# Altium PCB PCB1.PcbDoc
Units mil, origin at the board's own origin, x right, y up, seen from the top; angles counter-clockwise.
Board outline 2228.35 x 2228.35 mil, 2 copper layers (Top Layer, Bottom Layer); 19 components, 12 nets, 62 pads, 0 vias.
Unrouted connection lines stored in the file: 3.
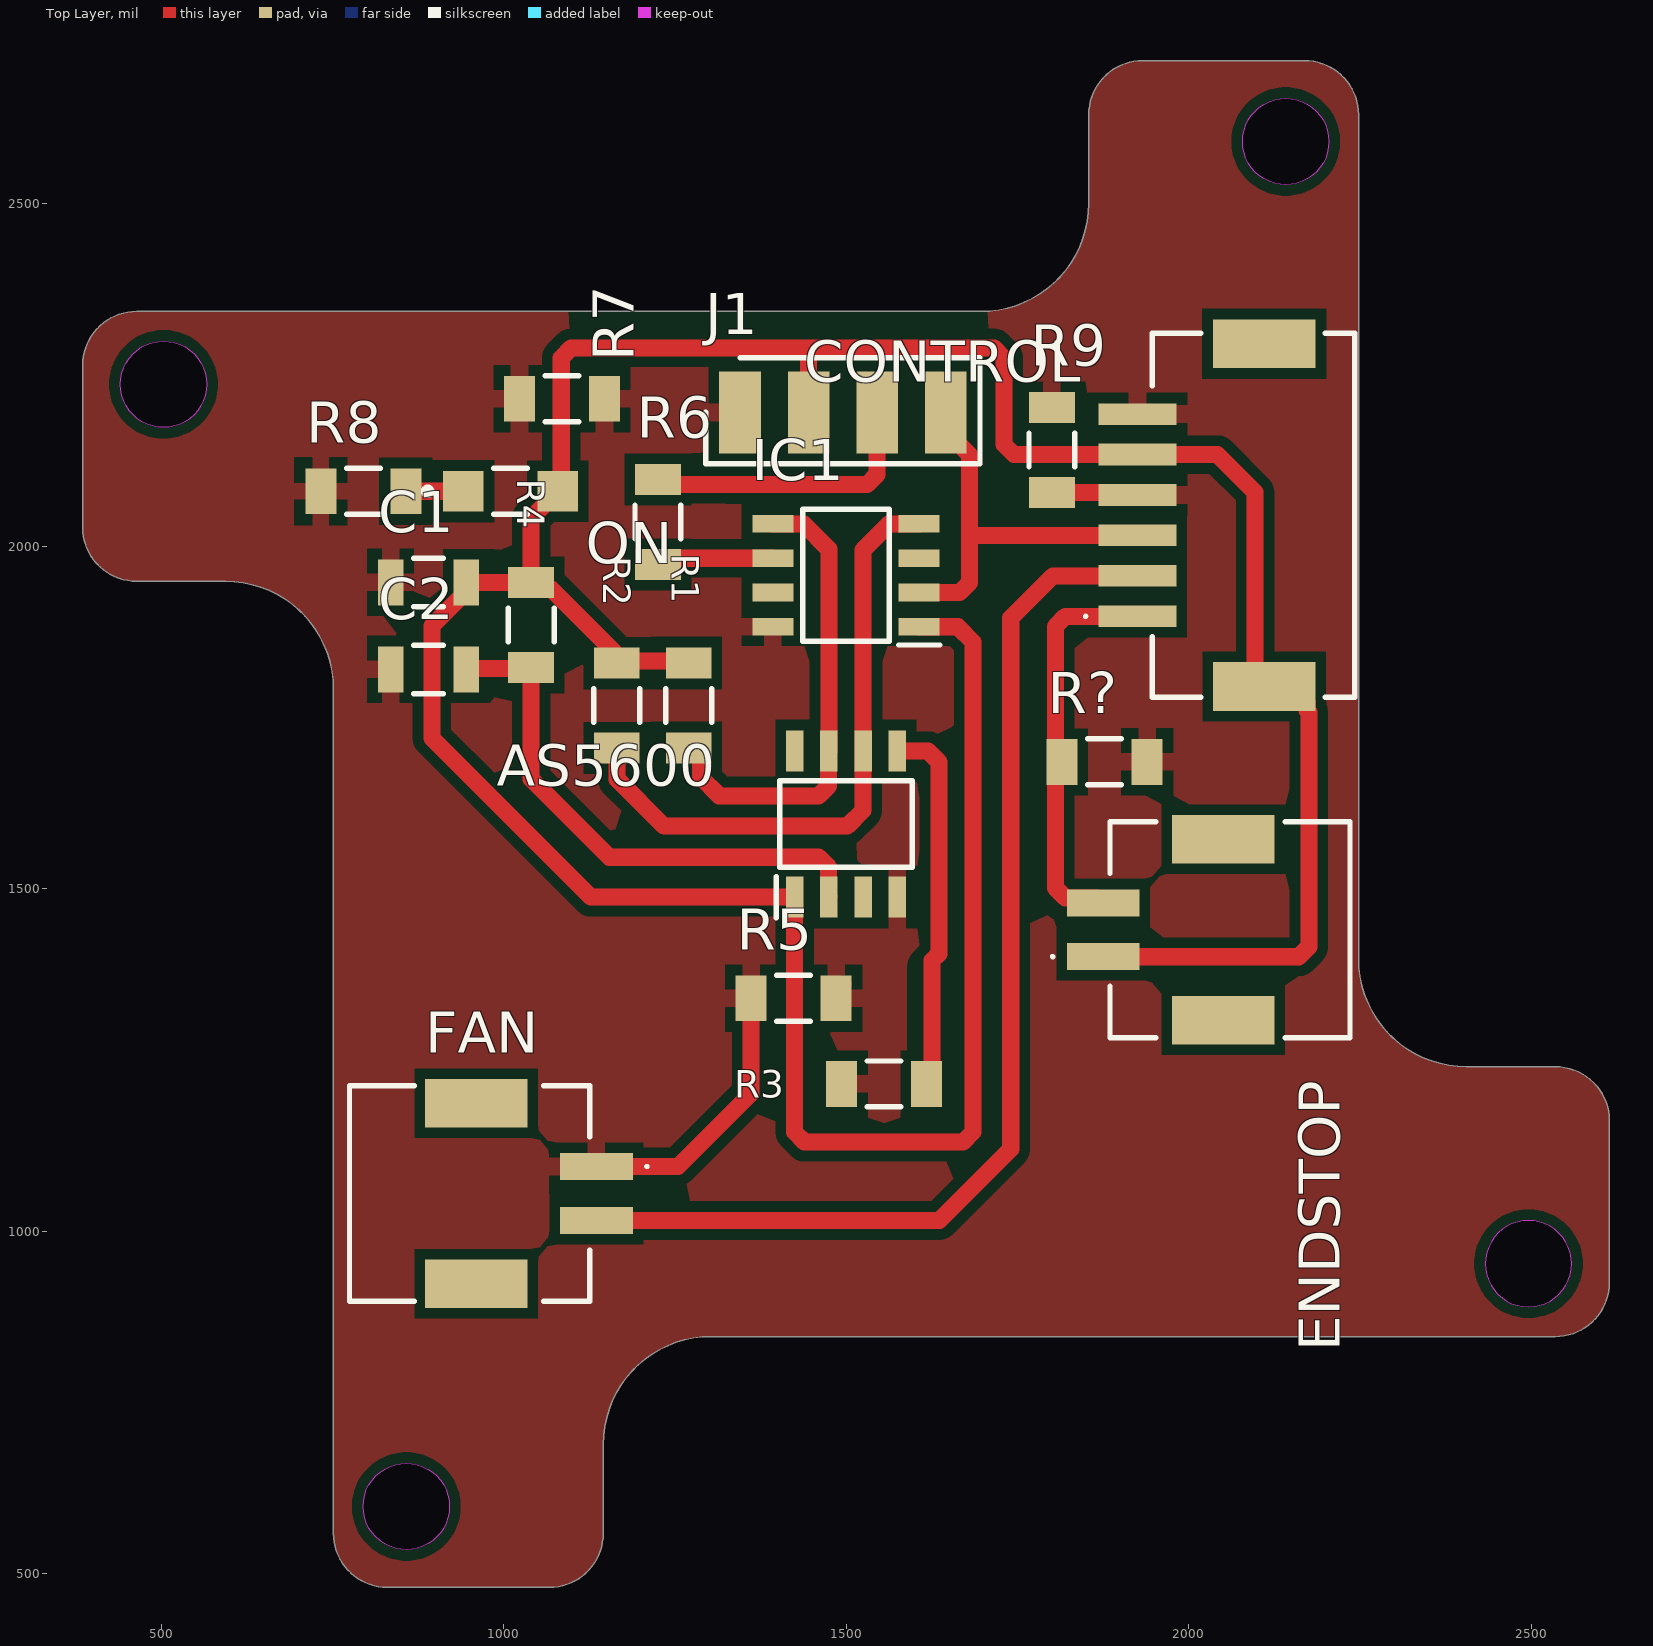
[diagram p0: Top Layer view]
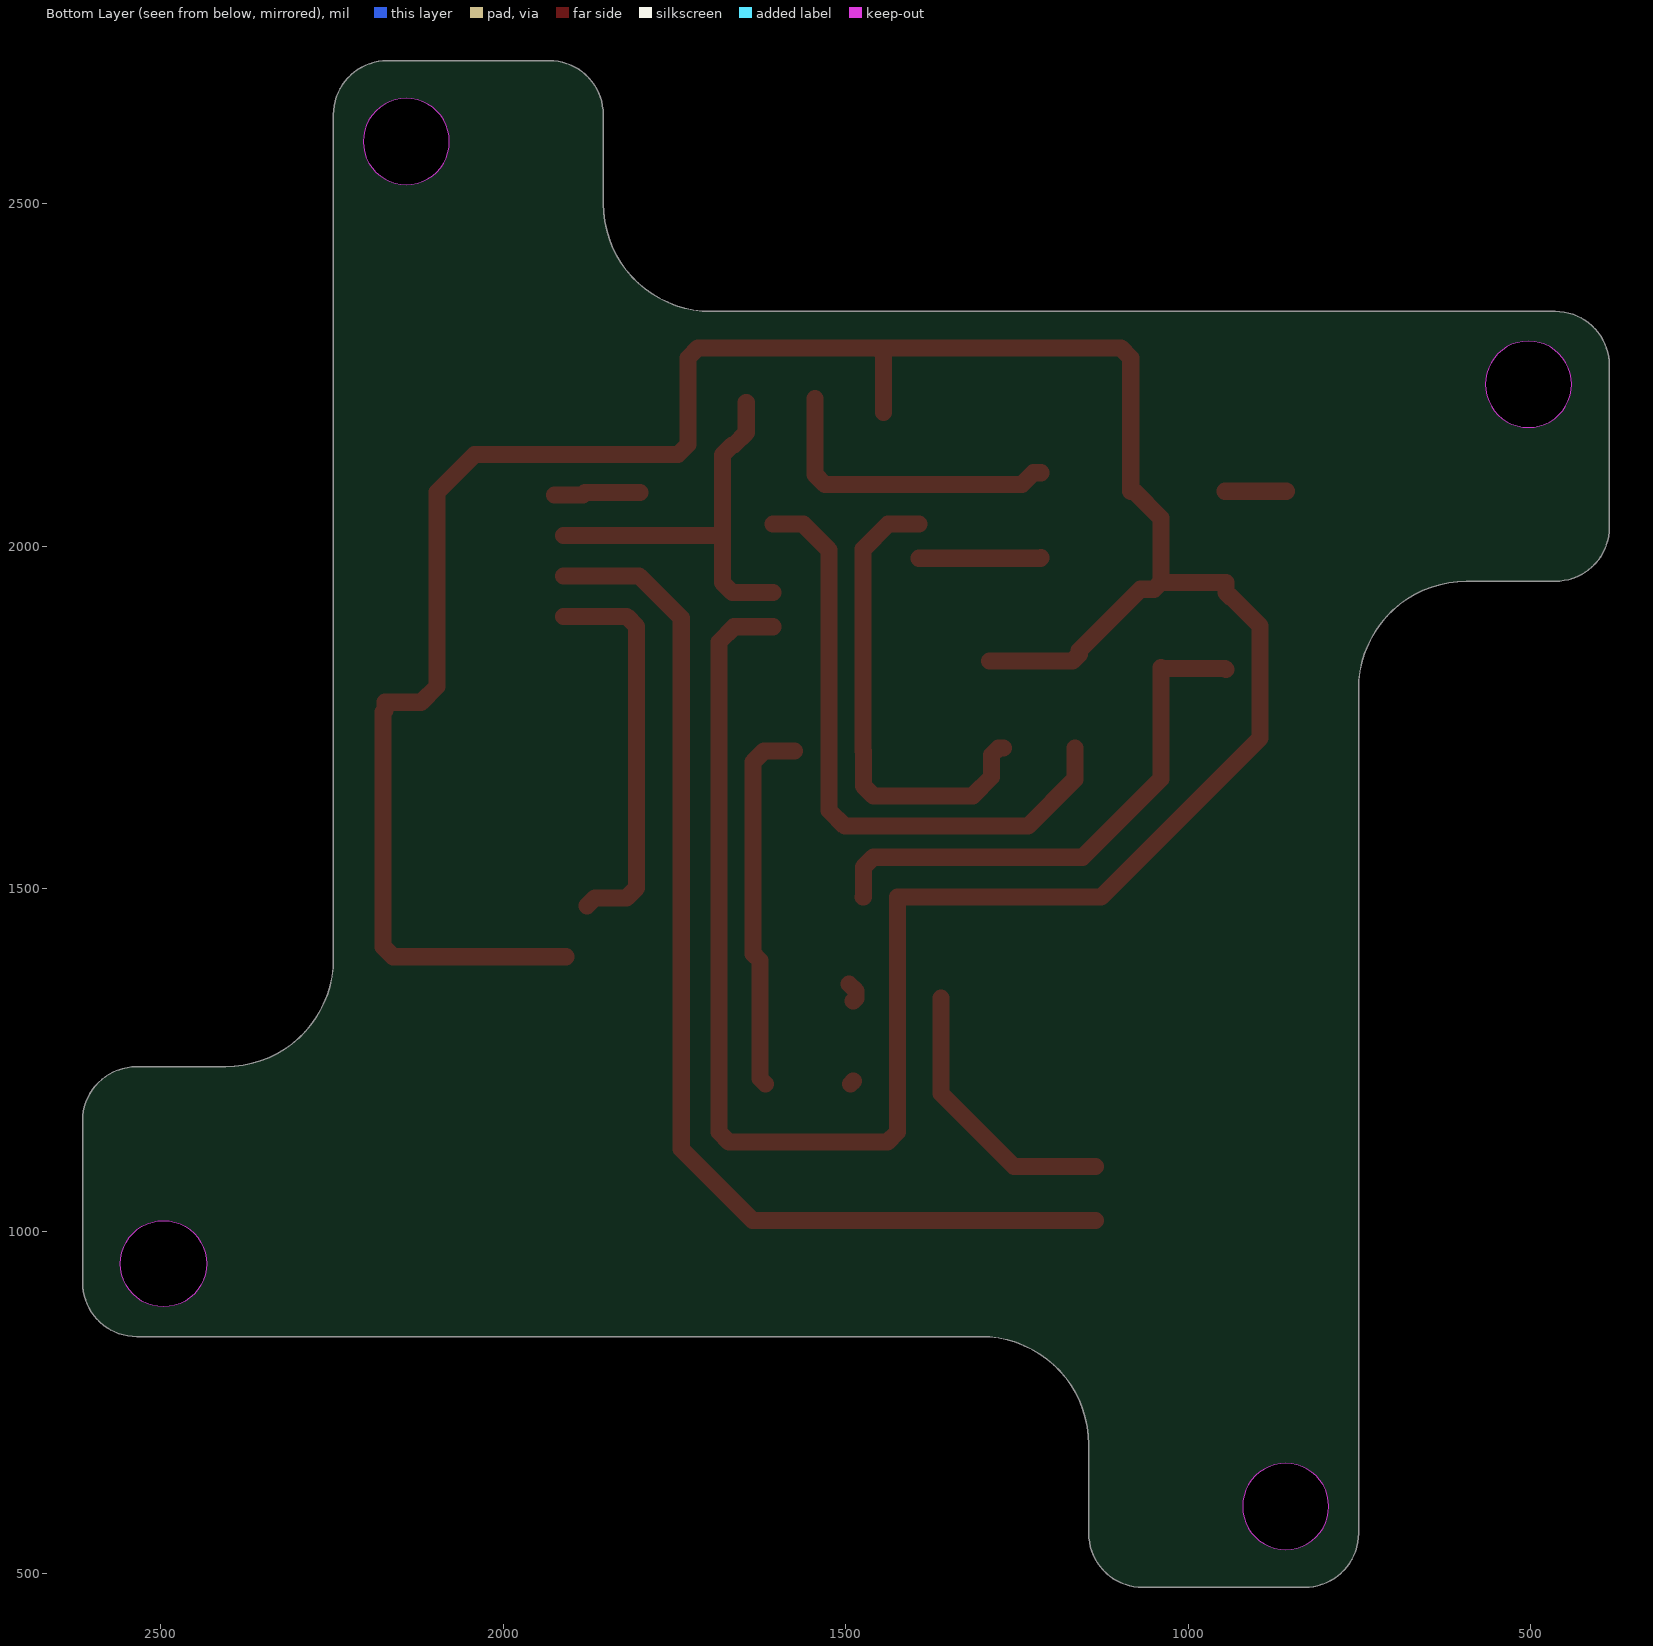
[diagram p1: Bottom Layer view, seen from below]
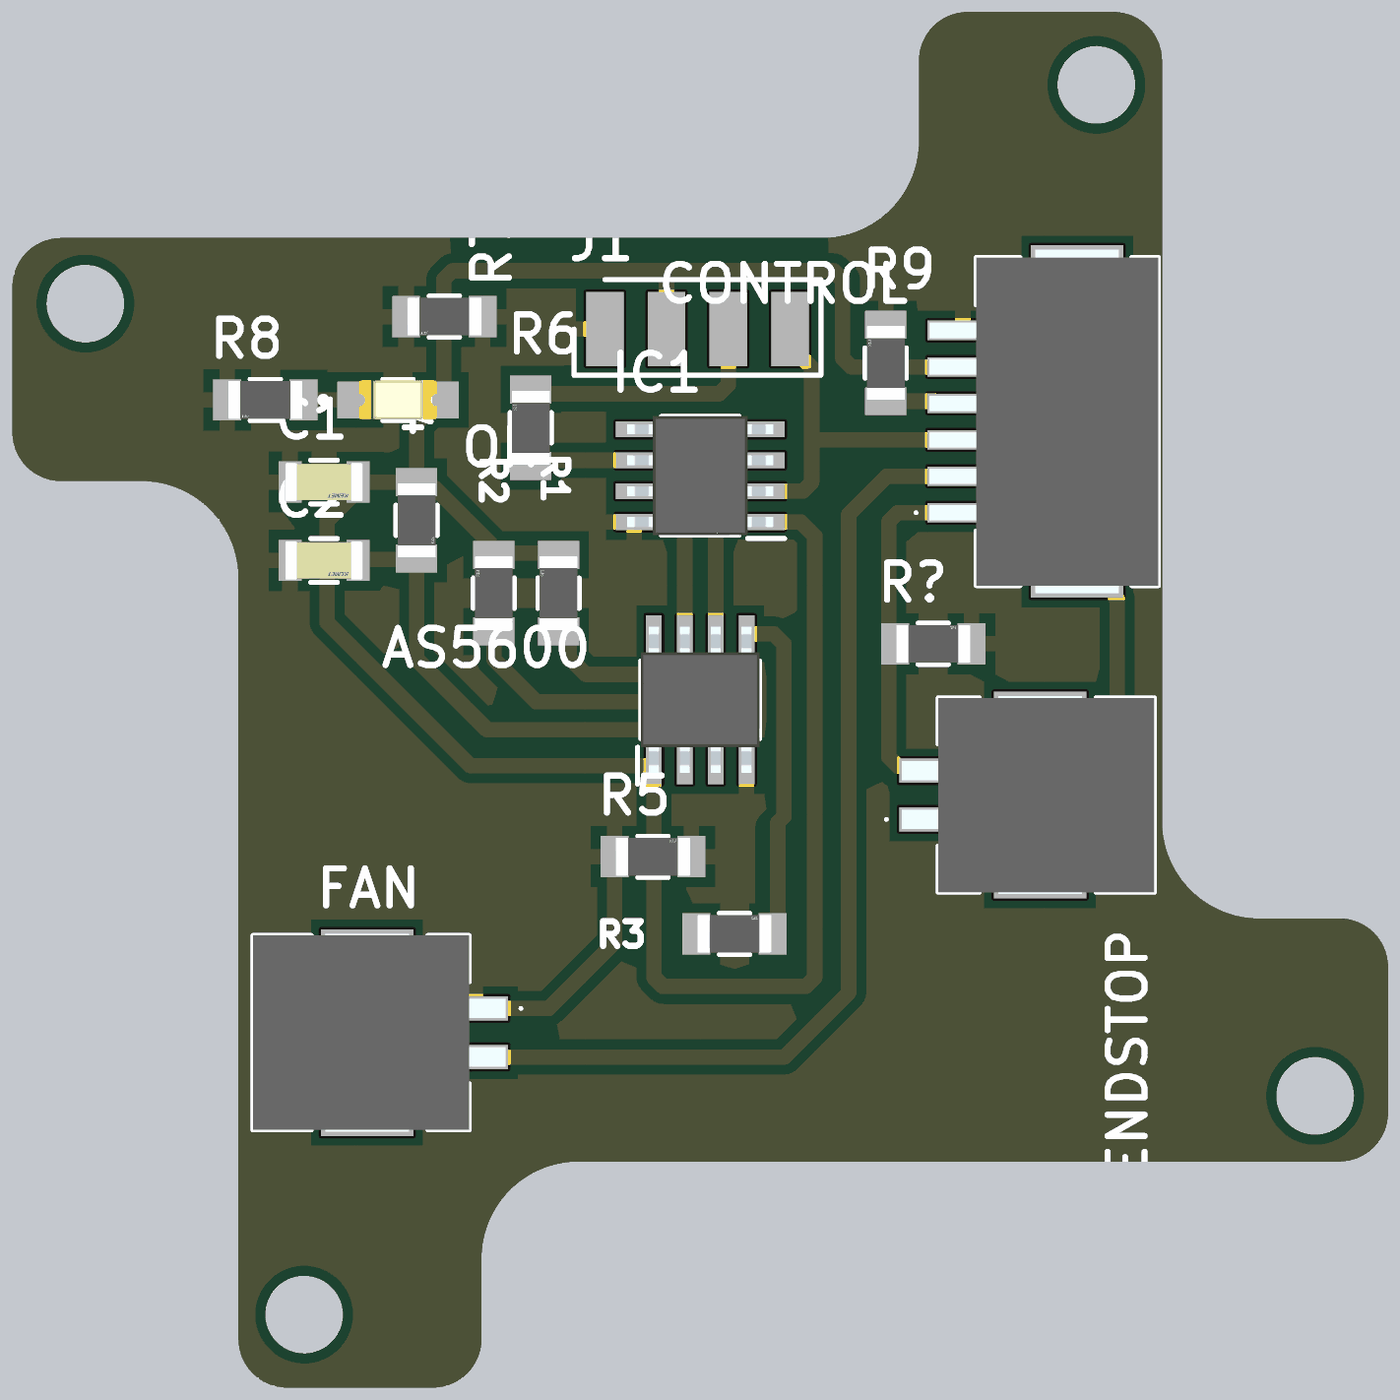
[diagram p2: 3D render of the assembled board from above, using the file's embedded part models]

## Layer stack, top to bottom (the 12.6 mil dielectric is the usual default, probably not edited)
Top Solder: solder mask 0.4, Solder Resist, Dk 3.5
Top Layer: signal copper 1.4
Dielectric 1: dielectric 12.6, FR-4, Dk 4.8
Bottom Layer: signal copper 1.4
Bottom Solder: solder mask 0.4, Solder Resist, Dk 3.5

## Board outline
751.46,558.9 ccw(c830.2,558.9) 830.2,480.16 1066.42,480.16 ccw(c1066.42,558.9) 1145.16,558.9 1145.16,688.82 cw(c1302.64,688.82) 1302.64,846.3 2534.92,846.3 ccw(c2534.92,925.04) 2613.66,925.04 2613.66,1161.26 ccw(c2534.92,1161.26) 2534.92,1240 2405,1240 cw(c2405,1397.48) 2247.52,1397.48 2247.52,2629.76 ccw(c2168.78,2629.76) 2168.78,2708.5 1932.56,2708.5 ccw(c1932.56,2629.76) 1853.82,2629.76 1853.82,2499.84 cw(c1696.34,2499.84) 1696.34,2342.36 464.06,2342.36 ccw(c464.06,2263.62) 385.31,2263.62 385.31,2027.4 ccw(c464.06,2027.4) 464.06,1948.66 593.98,1948.66 cw(c593.98,1791.18) 751.46,1791.18
cut-out: 2432.56,952.6 ccw(c2495.55,952.6) 2495.55,889.61 ccw(c2495.55,952.6) 2558.54,952.6 ccw(c2495.55,952.6) 2495.55,1015.59 ccw(c2495.55,952.6)
cut-out: 2141.22,2527.4 cw(c2141.22,2590.39) 2078.23,2590.39 cw(c2141.22,2590.39) 2141.22,2653.39 cw(c2141.22,2590.39) 2204.21,2590.39 cw(c2141.22,2590.39)
cut-out: 794.76,598.27 cw(c857.76,598.27) 857.76,661.26 cw(c857.76,598.27) 920.75,598.27 cw(c857.76,598.27) 857.76,535.28 cw(c857.76,598.27)
cut-out: 503.43,2173.07 cw(c503.43,2236.06) 440.43,2236.06 cw(c503.43,2236.06) 503.43,2299.06 cw(c503.43,2236.06) 566.42,2236.06 cw(c503.43,2236.06)

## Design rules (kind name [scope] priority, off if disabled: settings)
Clearance [All] p1: gap=15.75 ignorepadtopadclearanceinfootprint=FALSE
PlaneConnect [All] p1: planeconnectstyle=Relief reliefexpansion=20 reliefentries=4 reliefconductorwidth=30 reliefairgap=15.75
PolygonConnect [All] p1: connectstyle=Relief reliefconductorwidth=25 reliefentries=4 polygonreliefangle="90 Angle" conductorbypadedge=TRUE mindistance=15 enablemindistance=FALSE airgapwidth=16
RoutingVias [All] p1: holewidth=28 width=50 viastyle="Through Hole" minholewidth=28 minwidth=50 maxholewidth=28 maxwidth=50
SolderMaskExpansion [All] p1: expansion=4 istentingtop=FALSE
SupplyNets "Schematic Supply Nets_2" [InNet('+5')] p1: voltage=0.000
SupplyNets "Schematic Supply Nets_1" [InNet('+3.3')] p2: voltage=0.000
SupplyNets "Schematic Supply Nets" [InNet('GND')] p3: voltage=0.000
Width [All] p1: maxlimit=25 minlimit=25 preferedwidth=25
29 further rules are at their usual default settings.

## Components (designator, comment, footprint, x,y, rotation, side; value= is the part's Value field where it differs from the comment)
AS5600 "AS5600-ASOM" SOIC127P600X175-8N 1499.49,1594.33 r90 top
C1 "C1206C102K5HACAUTO" FP-C1206C-EB-MFG 890,1947.01 r180 top value="1,000 pF"
C2 "C1206C102K5HACAUTO" FP-C1206C-EB-MFG 890,1820 r180 top value="1,000 pF"
CONTROL "C" SM06BZESSTBLFSN 2083.43,2045 r270 top
ENDSTOP "SM02B-PASS-TBT__LF__SN_" SM02BPASSTBTLFSN 2055,1440 r270 top
FAN "SM02B-PASS-TBT__LF__SN_" SM02BPASSTBTLFSN 955,1055 r90 top
IC1 "ATTINY412-SSF" SOIC127P600X175-8N 1499.49,1957.23 r180 top
J1 "MTSW-104-07-G-S-000" HDRV4W64P0X254_1X4_1016X254X864P 1345,2195 r180 top
ON "LTST-C150AKT" FP-LTST-C150AKT-MFG 1010,2080 r0 top
R1 "CSR1206FT33L0" FP-CSR1206-MFG 1270,1767.01 r90 top
R2 "CSR1206FT33L0" FP-CSR1206-MFG 1165,1767.01 r90 top
R3 "CSR1206FT33L0" FP-CSR1206-MFG 1555,1215 r0 top
R4 "CSR1206FT33L0" FP-CSR1206-MFG 1040,1885 r270 top
R5 "CSR1206FT33L0" FP-CSR1206-MFG 1422.99,1340 r0 top
R6 "CSR1206FT33L0" FP-CSR1206-MFG 1225,2035 r90 top
R7 "CSR1206FT33L0" FP-CSR1206-MFG 1085,2215 r180 top
R8 "CSR1206FT33L0" FP-CSR1206-MFG 795,2080 r180 top
R9 "CSR1206FT33L0" FP-CSR1206-MFG 1800,2140 r90 top
R? "CSR1206FT33L0" FP-CSR1206-MFG 1877.01,1685 r0 top

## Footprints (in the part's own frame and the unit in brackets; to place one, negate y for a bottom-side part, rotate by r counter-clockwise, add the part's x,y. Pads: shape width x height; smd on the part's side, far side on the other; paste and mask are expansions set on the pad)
FP-C1206C-EB-MFG [mm]
  rect 0.95x1.7 smd paste+0 mask+0: 1(-1.4,0) 2(1.4,0)
  silkscreen extent -0.55,-0.9 0.55,0.9, body extent -2,-1 2,1, height 0.25
FP-CSR1206-MFG [mm]
  rect 1.15x1.7 smd paste+0 mask+0: 1(-1.575,0) 2(1.575,0)
  silkscreen extent -0.62,-0.85 0.62,0.85, body extent -2.25,-0.95 2.25,0.95, height 0.25
FP-LTST-C150AKT-MFG [mm]
  rect 1.5x1.5 smd paste+0 mask+0: 1(-1.75,0) 2(1.75,0)
  silkscreen extent -3.2,-0.85 0.62,0.85, body extent -2.6,-0.95 2.6,0.95, height 0.25
HDRV4W64P0X254_1X4_1016X254X864P [mil]
  rect 61.02x120 smd: 1(0,0) 2(-100,0) 3(-200,0) 4(-300,0)
  silkscreen extent -350,-80 50,75, body extent -350,-55 50,45, height 10
SM02BPASSTBTLFSN [mm]
  rect 1x2.7 smd: 1(1,-4.575) 2(-1,-4.575)
  rect 1.8x3.8 smd: 3(3.35,-0.125) 4(-3.35,-0.125)
  silkscreen extent -4,-6.5 4,4.57, body extent -4.07,-5.82 4.07,4.57, height 5.8
SM06BZESSTBLFSN [mm]
  rect 0.8x2.9 smd: 1(3.75,-4.025) 2(2.25,-4.025) 3(0.75,-4.025) 4(-0.75,-4.025) 5(-2.25,-4.025) 6(-3.75,-4.025)
  rect 1.8x3.8 smd: 7(6.35,0.675) 8(-6.35,0.675)
  silkscreen extent -6.75,-6 6.75,4.02, body extent -7.07,-5.4 7.07,4.03, height 5.9
SOIC127P600X175-8N [mm]
  rect 1.525x0.65 smd: 1(-2.712,1.905) 2(-2.712,0.635) 3(-2.712,-0.635) 4(-2.712,-1.905) 5(2.712,-1.905) 6(2.712,-0.635) 7(2.712,0.635) 8(2.712,1.905)
  silkscreen extent -3.47,-2.45 1.6,2.58, body extent -3,-2.45 3,2.45, height 1.75

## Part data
AS5600: "Integrated Circuit", Manufacturer_Name="ams OSRAM", Mouser Part Number=985-AS5600-ASOM
C1 C2: library part CMP-03020-003638-1, "C1206 1,000 pF X8R 10.00% 50 V", Capacitance="1,000 pF", Manufacturer=KEMET, Package=C1206C-EB, Temperature="-55°C to +150°C", Temperature Characteristic=X8R, Temperature Coefficient=15%, Temperature Range High=+150°C, Temperature Range Low=-55°C, Tolerance=0.1, Voltage Rating="50 V"
CONTROL: library part SM06B-ZESS-TB_LF__SN_, "Connector", Manufacturer_Name="JST (JAPAN SOLDERLESS TERMINALS)", Manufacturer_Part_Number=SM06B-ZESS-TB(LF)(SN)
ENDSTOP FAN: "Connector", Arrow Part Number="SM02B-PASS-TBT (LF)(SN)", Manufacturer_Name="JST (JAPAN SOLDERLESS TERMINALS)"
IC1: "Integrated Circuit", Manufacturer_Name=Microchip, Mouser Part Number=579-ATTINY412-SSF
J1: "Connector", Manufacturer_Name=SAMTEC
ON: library part CMP-22017-000004-1, "LED AMBER CLEAR SMD", Colour=Amber, Forward Current=30mA, Forward Voltage=2.1V, Manufacturer=Lite-On, Package=0, Power Dissipation=100mW, Reverse Voltage=5V, Temperature="-55°C to +85°C", Temperature Range High=+85°C, Temperature Range Low=-55°C
R1 R2 R3 R4 R5 R6 R7 R8 R9 R?: library part CMP-26527-002831-1, "General Purpose Thick Film Chip Resistor, 1206, 33mΩ, 1%, 0.5W", Case/Package=1206, Max Operating Temperature=155°C, Max Power Dissipation=500mW, Min Operating Temperature=-55°C, Package Quantity=5000, Resistance=33mR, Resistor Type="Thick Film", Temperature Coefficient=100ppm/°C, Tolerance=1%

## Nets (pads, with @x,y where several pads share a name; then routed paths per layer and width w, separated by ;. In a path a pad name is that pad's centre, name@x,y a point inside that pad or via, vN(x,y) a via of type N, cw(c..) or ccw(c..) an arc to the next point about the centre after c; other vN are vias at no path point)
+3.3: AS5600.2 C2.1 R4.2 | length 790.4
  Top Layer w25: C2.1 946.61,1821.5 1038.5,1821.5 R4.2 1040,1660 1154.17,1545.83 1459.55,1545.83 1474.19,1531.18 1474.19,1487.86 AS5600.2
+5: AS5600.1 C1.1 CONTROL.5 CONTROL.7 ENDSTOP.1 IC1.1 J1.2 ON.2 R1.2 R2.2 R4.1 | length 5309.5
  Top Layer w25: ON.2 1040,2041.1 R4.1 ; ON.2@1083.9,2080 1083.9,2274.61 1098.54,2289.25 1452.78,2289.25 ; R1.2@1290,1832.01 1169.17,1832.01 1159.04,1842.15 1159.04,1847.54 1069.7,1936.87 1050.14,1936.87 R4.1 ; J1.2 1445,2281.47 1452.78,2289.25 ; IC1.1 1662.77,1882.23 1685,1860 1685,1144.64 1670.36,1130 1439.13,1130 1424.49,1144.64 AS5600.1 1127.44,1487.56 895,1720 895,1883.37 937.68,1926.04 938.92,1926.04 945.12,1932.24 C1.1 R4.1 ; ENDSTOP.1@1908.3,1400.59 2160.36,1400.59 2175,1415.23 2175,1757.42 2172.3,1760.12 2172.3,1772.07 2119.51,1772.07 2096.57,1795 2096.57,2078.43 2041.42,2133.58 1911.54,2133.58 1744.64,2133.58 1730,2148.23 1730,2274.61 1715.36,2289.25 1452.78,2289.25
END: CONTROL.1 ENDSTOP.2 R?.1 | length 577.4
  Top Layer w25: ENDSTOP.2@1877.39,1475 1865.84,1486.56 1819.64,1486.56 1805,1501.2 1805,1615.98 1805,1690 1805,1882.72 1819.64,1897.36 CONTROL.1@1911.54,1897.36
FAN: CONTROL.2 FAN.2 | length 1620.1
  Top Layer w25: FAN.2 1635.63,1015.63 1740,1120 1740,1895 1801.42,1956.42 CONTROL.2@1911.54,1956.42
GND: AS5600.4 C1.2 C2.2 CONTROL.4 CONTROL.6 FAN.1 IC1.8 J1.1 R3.1 R5.1 R5.2 R7.1 R7.2 R8.2 R9.1 R9.2 R?.2 | length 567.5
  Top Layer w25: FAN.1 1254.37,1094.37 1360.98,1200.98 R5.1 ; R5.2 R5.2@1489,1336 ; R5.2@1485,1344.43 1485,1350.83 R5.2@1495.14,1360.96 ; R3.1@1489,1219 R3.1 ; R9.1 1880.16,2077.99 1883.62,2074.53 CONTROL.4
NetAS5600_5: AS5600.5 R3.2 | length 544.6
  Top Layer w25: AS5600.5 1618.9,1701.1 1635,1685 1635,1405 1625,1395 1625,1222.99 R3.2
NetIC1_6: IC1.6 R6.1 | length 178
  Top Layer w25: R6.1@1215,1982.99 1215.76,1982.23 IC1.6
NetON_1: ON.1 R8.1 | length 89.1
  Top Layer w25: R8.1 ON.1@946.1,2080
SCL: AS5600.7 IC1.5 R1.1 | length 700.3
  Top Layer w25: R1.1 1276.93,1705 1287.07,1694.86 1287.07,1662.93 1314.57,1635.43 1459.55,1635.43 1474.19,1650.07 1474.19,1700.81 AS5600.7 1474.49,1995.51 1438.07,2031.93 1393.01,2031.93 IC1.5
SDA: AS5600.6 IC1.4 R2.1 | length 920
  Top Layer w25: R2.1 1165.49,1704.51 1165.49,1659.51 1233.79,1591.21 1501.21,1591.21 1524.19,1614.19 1524.19,1700.81 AS5600.6 1524.49,1994.49 1561.93,2031.93 1605.96,2031.93 IC1.4
TX: CONTROL.3 IC1.2 J1.4 | length 590
  Top Layer w25: IC1.2 1665.36,1932.23 1680,1946.87 1680,2015.47 ; J1.4@1645,2209.64 1645,2165.51 1663.01,2147.5 1665.36,2147.5 1680,2132.86 1680,2015.47 ; CONTROL.3@1911.54,2015.47 1680,2015.47
UPDI: J1.3 R6.2 | length 453.5
  Top Layer w25: R6.2@1215,2107.01 1225.83,2107.01 1242.83,2090 1530.36,2090 1545,2104.64 J1.3@1545,2215
pads on no net: AS5600.3 AS5600.8 CONTROL.8 ENDSTOP.3 ENDSTOP.4 FAN.3 FAN.4 IC1.3 IC1.7

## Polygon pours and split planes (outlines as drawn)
GND on Top Layer "GND_L01_P000" (solid, pour order 0): 830.2,480.16 1066.42,480.16 ccw(c1066.42,558.9) 1145.16,558.9 1145.16,688.82 cw(c1302.64,688.82) 1302.64,846.3 2534.92,846.3 ccw(c2534.92,925.04) 2613.66,925.04 2613.66,1161.26 ccw(c2534.92,1161.26) 2534.92,1240 2405,1240 cw(c2405,1397.48) 2247.52,1397.48 2247.52,2629.76 ccw(c2168.78,2629.76) 2168.78,2708.5 1932.56,2708.5 ccw(c1932.56,2629.76) 1853.82,2629.76 1853.82,2499.84 cw(c1696.34,2499.84) 1696.34,2342.36 464.06,2342.36 ccw(c464.06,2263.62) 385.31,2263.62 385.32,2027.4 ccw(c464.06,2027.4) 464.06,1948.66 593.98,1948.66 cw(c593.98,1791.18) 751.46,1791.18 751.46,558.9 ccw(c830.2,558.9)

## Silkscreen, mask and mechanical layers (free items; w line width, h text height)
Mechanical 1:
  circle w1: c2495.55,952.6 r62.99
  circle w0.5: c503.43,2236.06 r62.99
  circle w0.5: c857.76,598.27 r62.99
  circle w0.5: c2141.22,2590.39 r62.99
  lines w0.5: 385.31,2027.4 ccw(c464.06,2027.4) 464.06,1948.66 593.98,1948.66 cw(c593.98,1791.18) 751.46,1791.18 751.46,558.9 ccw(c830.2,558.9) 830.2,480.16 1066.42,480.16 ccw(c1066.42,558.9) 1145.16,558.9 1145.16,688.82 cw(c1302.64,688.82) 1302.64,846.3 2534.92,846.3 ccw(c2534.92,925.04) 2613.66,925.04 2613.66,1161.26 ccw(c2534.92,1161.26) 2534.92,1240 2405,1240 cw(c2405,1397.48) 2247.52,1397.48 2247.52,2629.76 ccw(c2168.78,2629.76) 2168.78,2708.5 1932.56,2708.5 ccw(c1932.56,2629.76) 1853.82,2629.76 1853.82,2499.84 cw(c1696.34,2499.84) 1696.34,2342.36 464.06,2342.36 ccw(c464.06,2263.62) 385.31,2263.62 385.32,2027.4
